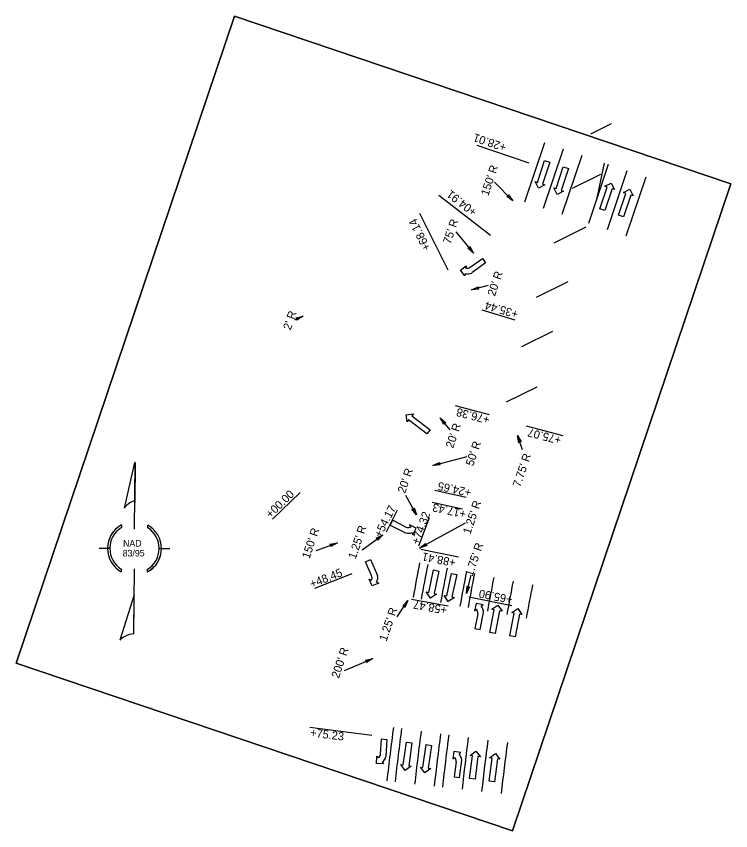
# Model space of a CAD drawing. Extents: x 1623150 to 1624004, y 886654 to 888237.
# Drawn here: x 1623149.5 to 1623584.5, y 886653.7 to 887149.3 of the extents above; entities that cross this region are included whole.
import ezdxf

# ---------------------------------------------------------------- set-up
doc = ezdxf.new("R2010")
doc.units = 0
for name, color, linetype in [('P_RDY_Dimension', 7, 'Continuous'), ('P_RDY_Dimension_Text', 7, 'Continuous'), ('P_RDY_Lane_Line', 7, 'Continuous'), ('P_RDY_Terminator_Cell', 7, 'Continuous'), ('Sheet_Plan_CELL', 7, 'Continuous'), ('Sheet_Sticker_Incomplete_CELL', 7, 'Continuous')]:
    doc.layers.add(name, color=color, linetype=linetype)

msp = doc.modelspace()

# ---------------------------------------------------------------- linework, layer by layer
at = {"layer": 'P_RDY_Dimension'}
for p, q in [((1623461.81, 887059.92), (1623430, 887070.66)), ((1623440.68, 887048.36), (1623451.85, 887036.95)), ((1623406.75, 887040.48), (1623438.3, 887016.06)), ((1623412.4, 886994.82), (1623395.26, 887029.27)), ((1623417.17, 887018.11), (1623427.96, 887005.15)), ((1623436.87, 886985.34), (1623426.62, 886982.83)), ((1623432.84, 886970.56), (1623453.02, 886964.57)), ((1623319.18, 886964.62), (1623324.09, 886966.83)), ((1623416.7, 886912.33), (1623437.43, 886906.99)), ((1623413.66, 886897.59), (1623407.59, 886904.84)), ((1623482.55, 886894.04), (1623460.19, 886899.78)), ((1623457.76, 886885.49), (1623454.55, 886894.19)), ((1623403.04, 886875.84), (1623424.11, 886881.31)), ((1623305.4, 886843.19), (1623322.32, 886859.45)), ((1623404.32, 886860.87), (1623423.3, 886856.62)), ((1623393.25, 886845.8), (1623386.6, 886857.64)), ((1623402.72, 886853.66), (1623421.13, 886849.63)), ((1623374.92, 886835.63), (1623381.63, 886848.85)), ((1623394.63, 886827.01), (1623401.01, 886844.25)), ((1623422.89, 886840.71), (1623395.06, 886825.67)), ((1623360.16, 886824.65), (1623372.77, 886833.74)), ((1623332.04, 886824.14), (1623344.99, 886828.91)), ((1623418.73, 886820.17), (1623395.9, 886824.74)), ((1623331.22, 886801.22), (1623353.9, 886810.08)), ((1623423.57, 886797.99), (1623426.45, 886809.18)), ((1623390.16, 886794.64), (1623412.46, 886790.6)), ((1623424.96, 886795.95), (1623451.3, 886790.78)), ((1623381.33, 886783.78), (1623387.95, 886793.77)), ((1623349.39, 886751.25), (1623366.49, 886758.43)), ((1623328.19, 886716.71), (1623365.99, 886711.86))]:
    msp.add_line(p, q, dxfattribs=at)
msp.add_lwpolyline([(1623149.52, 886755.58), (1623451.65, 886653.66), (1623584.45, 887047.34), (1623282.32, 887149.26)], close=True, dxfattribs=at)
at = {"layer": 'P_RDY_Lane_Line'}
for p, q in [((1623499.24, 887077.81), (1623511.91, 887084.09)), ((1623459.16, 887036.42), (1623471.29, 887072.37)), ((1623470.53, 887032.59), (1623482.66, 887068.53)), ((1623481.9, 887028.75), (1623494.03, 887064.69)), ((1623466.75, 887048.21), (1623471.17, 887061.5)), ((1623474.3, 887060.46), (1623469.88, 887047.17)), ((1623471.17, 887061.5), (1623474.3, 887060.46)), ((1623478.12, 887044.38), (1623482.54, 887057.66)), ((1623482.54, 887057.66), (1623485.67, 887056.62)), ((1623498.01, 887023.32), (1623510.13, 887059.26)), ((1623503.2, 887038.7), (1623507.6, 887059.79)), ((1623485.67, 887056.62), (1623481.25, 887043.34)), ((1623488.06, 887044.65), (1623505.48, 887053.28)), ((1623509.38, 887019.48), (1623521.51, 887055.42)), ((1623467.37, 887044.69), (1623465.33, 887048.69)), ((1623465.33, 887048.69), (1623466.75, 887048.21)), ((1623507.76, 887045.8), (1623511.69, 887047.81)), ((1623511.69, 887047.81), (1623513.74, 887043.82)), ((1623520.75, 887015.65), (1623532.88, 887051.59)), ((1623471.3, 887046.7), (1623467.37, 887044.69)), ((1623469.88, 887047.17), (1623471.3, 887046.7)), ((1623478.74, 887040.85), (1623476.7, 887044.85)), ((1623476.7, 887044.85), (1623478.12, 887044.38)), ((1623482.67, 887042.86), (1623478.74, 887040.85)), ((1623481.25, 887043.34), (1623482.67, 887042.86)), ((1623504.78, 887032.04), (1623509.18, 887045.33)), ((1623509.18, 887045.33), (1623507.76, 887045.8)), ((1623512.31, 887044.29), (1623507.91, 887031)), ((1623513.74, 887043.82), (1623512.31, 887044.29)), ((1623519.13, 887041.96), (1623523.06, 887043.98)), ((1623523.06, 887043.98), (1623525.11, 887039.98)), ((1623516.15, 887028.2), (1623520.55, 887041.49)), ((1623520.55, 887041.49), (1623519.13, 887041.96)), ((1623523.69, 887040.45), (1623519.28, 887027.16)), ((1623525.11, 887039.98), (1623523.69, 887040.45)), ((1623507.91, 887031), (1623504.78, 887032.04)), ((1623519.28, 887027.16), (1623516.15, 887028.2)), ((1623476.89, 887011.5), (1623496.51, 887021.22)), ((1623425.93, 886996.54), (1623433.31, 887001.95)), ((1623435.26, 886999.28), (1623426.75, 886993.05)), ((1623433.31, 887001.95), (1623435.26, 886999.28)), ((1623419.86, 886994.76), (1623423.46, 886997.46)), ((1623422.5, 886991.24), (1623419.86, 886994.76)), ((1623423.46, 886997.46), (1623423.24, 886995.99)), ((1623422.73, 886992.71), (1623422.5, 886991.24)), ((1623466.27, 886978.32), (1623485.5, 886987.84)), ((1623457.32, 886948.26), (1623476.2, 886957.62)), ((1623448.05, 886914.65), (1623466.57, 886923.83)), ((1623386.8, 886906.78), (1623391.25, 886907.4)), ((1623387.42, 886902.4), (1623386.8, 886906.78)), ((1623391.25, 886907.4), (1623390.34, 886906.21)), ((1623390.34, 886906.21), (1623401.45, 886897.7)), ((1623388.33, 886903.59), (1623387.42, 886902.4)), ((1623399.45, 886895.08), (1623388.33, 886903.59)), ((1623401.45, 886897.7), (1623399.45, 886895.08)), ((1623378.55, 886842.6), (1623377.06, 886839.65)), ((1623377.06, 886839.65), (1623386.48, 886834.89)), ((1623386.72, 886838.47), (1623378.55, 886842.6)), ((1623393, 886837.7), (1623389, 886839.78)), ((1623389, 886839.78), (1623389.47, 886838.37)), ((1623390.5, 886835.21), (1623390.97, 886833.8)), ((1623390.97, 886833.8), (1623393, 886837.7)), ((1623362.18, 886817.3), (1623365.21, 886818.61)), ((1623365.81, 886808.9), (1623362.18, 886817.3)), ((1623365.21, 886818.61), (1623369.4, 886808.93)), ((1623400.61, 886798.63), (1623403.5, 886812.33)), ((1623403.5, 886812.33), (1623406.73, 886811.65)), ((1623406.73, 886811.65), (1623403.84, 886797.95)), ((1623411.53, 886796.58), (1623414.42, 886810.28)), ((1623414.42, 886810.28), (1623417.65, 886809.59)), ((1623417.65, 886809.59), (1623414.76, 886795.9)), ((1623366.2, 886802.59), (1623364.37, 886806.7)), ((1623364.37, 886806.7), (1623365.75, 886806.15)), ((1623368.84, 886804.93), (1623370.22, 886804.38)), ((1623370.22, 886804.38), (1623366.2, 886802.59)), ((1623401.62, 886795.2), (1623399.14, 886798.94)), ((1623399.14, 886798.94), (1623400.61, 886798.63)), ((1623405.3, 886797.64), (1623401.62, 886795.2)), ((1623403.84, 886797.95), (1623405.3, 886797.64)), ((1623412.54, 886793.14), (1623410.06, 886796.89)), ((1623410.06, 886796.89), (1623411.53, 886796.58)), ((1623416.23, 886795.59), (1623412.54, 886793.14)), ((1623414.76, 886795.9), (1623416.23, 886795.59)), ((1623429.42, 886791.96), (1623428.52, 886787.55)), ((1623433.73, 886791.08), (1623429.42, 886791.96)), ((1623432.5, 886790.25), (1623433.73, 886791.08)), ((1623439.04, 886788.38), (1623442.68, 886790.89)), ((1623442.68, 886790.89), (1623445.23, 886787.19)), ((1623428.52, 886787.55), (1623429.75, 886788.38)), ((1623430.41, 886785.71), (1623428.69, 886776.72)), ((1623431.93, 886776.1), (1623433.91, 886786.46)), ((1623437.88, 886774.35), (1623440.52, 886788.1)), ((1623440.52, 886788.1), (1623439.04, 886788.38)), ((1623443.76, 886787.47), (1623441.12, 886773.72)), ((1623445.23, 886787.19), (1623443.76, 886787.47)), ((1623449.97, 886772.33), (1623452.61, 886786.08)), ((1623451.13, 886786.36), (1623454.77, 886788.87)), ((1623452.61, 886786.08), (1623451.13, 886786.36)), ((1623455.85, 886785.46), (1623453.21, 886771.71)), ((1623454.77, 886788.87), (1623457.32, 886785.17)), ((1623457.32, 886785.17), (1623455.85, 886785.46)), ((1623428.69, 886776.72), (1623431.93, 886776.1)), ((1623441.12, 886773.72), (1623437.88, 886774.35)), ((1623453.21, 886771.71), (1623449.97, 886772.33)), ((1623371.3, 886700.34), (1623371.88, 886709.47)), ((1623371.88, 886709.47), (1623375.17, 886709.26)), ((1623375.17, 886709.26), (1623374.5, 886698.73)), ((1623385.13, 886693.67), (1623387.14, 886707.52)), ((1623387.14, 886707.52), (1623390.41, 886707.05)), ((1623390.41, 886707.05), (1623388.4, 886693.19)), ((1623397.04, 886692.18), (1623399.05, 886706.04)), ((1623399.05, 886706.04), (1623402.32, 886705.56)), ((1623402.32, 886705.56), (1623400.3, 886691.71)), ((1623415.85, 886701.78), (1623415.24, 886697.32)), ((1623420.21, 886701.18), (1623415.85, 886701.78)), ((1623419.04, 886700.27), (1623420.21, 886701.18)), ((1623425.78, 886699.42), (1623429.25, 886702.16)), ((1623429.25, 886702.16), (1623432.03, 886698.63)), ((1623437.69, 886697.91), (1623441.16, 886700.65)), ((1623441.16, 886700.65), (1623443.94, 886697.12)), ((1623368.77, 886694.54), (1623369.01, 886699.03)), ((1623369.01, 886699.03), (1623369.99, 886697.92)), ((1623415.24, 886697.32), (1623416.41, 886698.23)), ((1623417.24, 886695.61), (1623416.09, 886686.53)), ((1623419.37, 886686.12), (1623420.69, 886696.58)), ((1623425.52, 886685.34), (1623427.27, 886699.23)), ((1623427.27, 886699.23), (1623425.78, 886699.42)), ((1623430.55, 886698.82), (1623428.79, 886684.93)), ((1623432.03, 886698.63), (1623430.55, 886698.82)), ((1623437.42, 886683.84), (1623439.18, 886697.73)), ((1623439.18, 886697.73), (1623437.69, 886697.91)), ((1623442.45, 886697.31), (1623440.7, 886683.42)), ((1623443.94, 886697.12), (1623442.45, 886697.31)), ((1623373.17, 886694.31), (1623368.77, 886694.54)), ((1623372.19, 886695.42), (1623373.17, 886694.31)), ((1623386.36, 886690.31), (1623383.65, 886693.88)), ((1623383.65, 886693.88), (1623385.13, 886693.67)), ((1623389.88, 886692.98), (1623386.36, 886690.31)), ((1623388.4, 886693.19), (1623389.88, 886692.98)), ((1623398.27, 886688.82), (1623395.55, 886692.4)), ((1623395.55, 886692.4), (1623397.04, 886692.18)), ((1623401.79, 886691.49), (1623398.27, 886688.82)), ((1623400.3, 886691.71), (1623401.79, 886691.49)), ((1623416.09, 886686.53), (1623419.37, 886686.12)), ((1623428.79, 886684.93), (1623425.52, 886685.34)), ((1623440.7, 886683.42), (1623437.42, 886683.84))]:
    msp.add_line(p, q, dxfattribs=at)
for centre, radius, start, end in [((1623424.33, 886997.69), 5.25, 252.2323, 297.544), ((1623424, 886999.16), 3.27, 256.5619, 306.2201), ((1623388.11, 886839.87), 5.25, 251.8584, 297.1701), ((1623388.2, 886841.37), 3.27, 243.1824, 292.8406), ((1625016.97, 886500.13), 1652.5, 168.95718, 169.70303), ((1625016.97, 886500.13), 1647.5, 168.95718, 169.70303), ((1625016.97, 886500.13), 1635.5, 168.95718, 169.70303), ((1625016.97, 886500.13), 1623.5, 168.95718, 169.70303), ((1625016.97, 886500.13), 1618.5, 168.95718, 169.70303), ((1623362.83, 886807.6), 3.27, 333.7298, 23.388), ((1623364.33, 886807.6), 5.25, 329.4003, 14.7119), ((1625016.97, 886500.13), 1606.5, 168.95718, 169.70303), ((1625016.97, 886500.13), 1594.5, 168.95718, 169.70303), ((1625016.97, 886500.13), 1582.5, 168.95718, 169.70303), ((1623428.68, 886786.66), 5.25, 357.8306, 43.1423), ((1623427.21, 886786.33), 3.27, 349.1545, 38.8127), ((1625017.39, 886500.08), 1652.5, 172.47754, 173.61278), ((1625017.39, 886500.08), 1647.5, 172.47754, 173.61278), ((1625017.39, 886500.08), 1635.5, 172.47754, 173.61278), ((1625017.39, 886500.08), 1623.5, 172.47754, 173.61278), ((1625017.39, 886500.08), 1618.5, 172.47754, 173.61278), ((1625017.39, 886500.08), 1606.5, 172.47754, 173.60718), ((1625017.39, 886500.08), 1594.5, 172.47754, 173.60718), ((1625017.39, 886500.08), 1582.5, 172.47754, 173.60718), ((1623368.04, 886700.54), 3.27, 306.699, 356.3571), ((1623369.39, 886699.85), 5.25, 302.3694, 347.6811), ((1623414.01, 886696.03), 3.27, 352.8058, 42.464), ((1623415.46, 886696.45), 5.25, 1.4819, 46.7936)]:
    msp.add_arc(centre, radius, start, end, dxfattribs=at)
at = {"layer": 'P_RDY_Terminator_Cell'}
for points in [[(1623449.26, 887040.7), (1623451.85, 887036.95), (1623448.12, 887039.62), (1623449.09, 887039.77)], [(1623425.67, 887009.11), (1623427.96, 887005.15), (1623424.45, 887008.12), (1623425.43, 887008.19)], [(1623431.17, 886983.14), (1623426.62, 886982.83), (1623430.82, 886984.68), (1623430.45, 886983.77)], [(1623319.66, 886965.69), (1623324.09, 886966.83), (1623320.29, 886964.24), (1623320.48, 886965.21)], [(1623409.88, 886900.89), (1623407.59, 886904.84), (1623411.11, 886901.89), (1623410.12, 886901.81)], [(1623455.38, 886889.7), (1623454.55, 886894.19), (1623456.87, 886890.22), (1623455.92, 886890.48)], [(1623407.59, 886876.22), (1623403.04, 886875.84), (1623407.22, 886877.75), (1623406.87, 886876.83)], [(1623391.72, 886850.1), (1623393.25, 886845.8), (1623390.34, 886849.35), (1623391.31, 886849.25)], [(1623368.66, 886831.73), (1623372.77, 886833.74), (1623369.57, 886830.44), (1623369.56, 886831.43)], [(1623340.5, 886828.08), (1623344.99, 886828.91), (1623341.02, 886826.59), (1623341.28, 886827.54)], [(1623399.39, 886827.13), (1623395.06, 886825.67), (1623398.66, 886828.53), (1623398.54, 886827.55)], [(1623425.44, 886802.15), (1623423.57, 886797.99), (1623423.92, 886802.57), (1623424.55, 886801.81)], [(1623384.82, 886790.45), (1623387.95, 886793.77), (1623386.12, 886789.56), (1623385.77, 886790.48)], [(1623362.04, 886757.4), (1623366.49, 886758.43), (1623362.63, 886755.94), (1623362.85, 886756.9)]]:
    msp.add_lwpolyline(points, close=True, dxfattribs=at)
at = {"layer": 'Sheet_Plan_CELL'}
msp.add_lwpolyline([(1623584.45, 887047.34), (1623451.65, 886653.66), (1623149.52, 886755.58), (1623282.32, 887149.26)], close=True, dxfattribs=at)
at = {"layer": 'Sheet_Sticker_Incomplete_CELL'}
for p, q in [((1623215.31, 886849.95), (1623221.79, 886877.72)), ((1623221.56, 886837.19), (1623221.82, 886877.72)), ((1623221.82, 886877.72), (1623221.66, 886853.35)), ((1623221.82, 886877.72), (1623221.79, 886877.72)), ((1623221.82, 886877.72), (1623221.79, 886877.72)), ((1623221.66, 886853.35), (1623221.67, 886854.03)), ((1623221.67, 886854.03), (1623221.68, 886854.03)), ((1623213.51, 886839.78), (1623213.5, 886838.15)), ((1623213.51, 886839.8), (1623213.51, 886839.78)), ((1623229.64, 886838.03), (1623229.65, 886839.66)), ((1623199.88, 886825.59), (1623206.48, 886825.54)), ((1623206.48, 886825.54), (1623205.08, 886825.55)), ((1623205.08, 886825.55), (1623206.48, 886825.54)), ((1623236.48, 886825.35), (1623243.08, 886825.31)), ((1623236.48, 886825.35), (1623237.88, 886825.34)), ((1623237.88, 886825.34), (1623236.48, 886825.35)), ((1623213.34, 886812.85), (1623213.33, 886811.22)), ((1623221.14, 886773.17), (1623221.4, 886813.11)), ((1623229.47, 886811.12), (1623229.48, 886812.76)), ((1623229.47, 886811.11), (1623229.47, 886811.12)), ((1623221.28, 886797.17), (1623212.5, 886769.65)), ((1623221.15, 886773.17), (1623221.28, 886797.17))]:
    msp.add_line(p, q, dxfattribs=at)
for radius, start, end in [(16.4, 119.0636, 240.1952), (16.4, 299.1498, 60.109), (16.4, 359.6294, 60.109), (15, 122.1326, 237.1262), (15, 302.23, 57.0288), (15, 359.6294, 57.0288), (16.4, 179.6294, 240.1952), (15, 179.6294, 237.1262)]:
    msp.add_arc((1623221.48, 886825.45), radius, start, end, dxfattribs=at)
for centre, major_axis, ratio, start_param, end_param in [((1623218.44, 886851.66), (3.21, 2.43), 0.261723, 6.225794, 8.917625), ((1623221.48, 886825.45), (0.11, 16.42), 0.998737, 0.514018, 1.570796), ((1623221.48, 886825.45), (0.1, 15.02), 0.998737, 0.567287, 1.570796), ((1623221.48, 886825.45), (0.11, 16.42), 0.998737, 3.657116, 4.712389), ((1623221.48, 886825.45), (0.1, 15.02), 0.998737, 3.71058, 4.712389), ((1623216.82, 886771.26), (4.32, 1.91), 0.225493, 6.280036, 9.220301)]:
    msp.add_ellipse(centre, major_axis=major_axis, ratio=ratio, start_param=start_param, end_param=end_param, dxfattribs=at)

# ---------------------------------------------------------------- texts
at = {"layer": 'P_RDY_Dimension'}
for s, p in [("150' R", (1623436.86, 887039.62)), ("75' R", (1623413.84, 887010.31)), ("20' R", (1623440.87, 886978.57)), ("2' R", (1623316.52, 886957.95)), ("20' R", (1623415.46, 886886.05)), ("50' R", (1623427.65, 886875.17)), ("7.75' R", (1623456.36, 886862.39)), ("20' R", (1623386.21, 886858.6)), ("1.25' R", (1623425.95, 886833.71)), ("1.25' R", (1623356.11, 886818.56)), ("150' R", (1623328.01, 886818.8)), ("1.75' R", (1623427.23, 886808.03)), ("1.25' R", (1623374.9, 886768.59)), ("200' R", (1623345.88, 886746.07))]:
    msp.add_text(s, height=5, rotation=71.3589, dxfattribs=at).set_placement(p)
at = {"layer": 'P_RDY_Dimension_Text'}
for s, rotation, p in [('+28.01', 161.3589, (1623448.32, 887071.46)), ('+04.91', 142.2603, (1623430.34, 887031.21)), ('+68.14', 116.4554, (1623401.94, 887008.18)), ('+35.44', 163.4604, (1623455.51, 886970.07)), ('+76.38', 165.5558, (1623438.17, 886905.83)), ('+75.07', 165.6023, (1623481.63, 886893.45)), ('+24.65', 167.391, (1623426.89, 886861.53)), ('+00.00', 43.871, (1623304.29, 886843.57)), ('+54.17', 62.9023, (1623371.47, 886831.65)), ('+17.43', 167.6471, (1623423.72, 886848.54)), ('+74.32', 69.6793, (1623394.49, 886827.33)), ('+88.41', 168.6767, (1623417.39, 886818.97)), ('+48.45', 21.34, (1623329.38, 886801.31)), ('+65.90', 168.904, (1623451.97, 886796.56)), ('+58.47', 169.7387, (1623412.06, 886790.14)), ('+75.23', 352.6921, (1623328.21, 886711.04))]:
    msp.add_text(s, height=5, rotation=rotation, dxfattribs=at).set_placement(p)
at = {"layer": 'Sheet_Sticker_Incomplete_CELL'}
for s, p in [('NAD', (1623214.53, 886826.55)), ('83/95', (1623214.28, 886820.55))]:
    msp.add_text(s, height=4, dxfattribs=at).set_placement(p)

doc.saveas('drawing.dxf')
